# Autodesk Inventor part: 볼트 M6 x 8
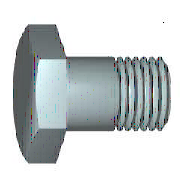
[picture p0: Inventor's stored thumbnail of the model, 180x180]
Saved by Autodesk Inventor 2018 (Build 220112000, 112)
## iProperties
Created: 2012-02
Part Number: 볼트 M6 x 8
Material: 강철, 연강
Description: 6각 머리 볼트 및 6각 머리 나사
Document SubType Name: Modeling
Standard: KS B 1002
Designer: mduedu
Standards Organization: KS
Language: ko-KR
Size Designation: C  M 6 x 12
Categories: <MemberInstance><Categories><Category DisplayName="조임쇠" InternalName="e4da775c-781d-43d5-af7c-5136215cf5a6" Mnemonic="FSTN"><Category DisplayName="볼트" InternalN
Density: 7.86 g/cm^3
Mass: 4.46616 g
Surface Area: 4.51243 cm^2
Volume: 0.568214 cm^3
Appearance: 강철
IsCustomPart: 1
Author: mduedu
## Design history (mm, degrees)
sketch "스케치1"
  geometry: L1 (0, 3)-(8, 3); L2 (8, 3)-(8, 0); L3 (8, 0)-(0, 0); L4 (-2.4, 0)-(14.4, 0) reference; L5 (0, -0.6)-(0, 3.6) reference; L6 (0, 3)-(0, 0)
  constraints: 8 end point, 3 point on line, 1 collinear
  dimensions: "d2" = 6 diameter of L1 L3 (= GD); "d59" = 8 distance between parallel lines of L2 L5 (= NLG)
revolve "본체" sketch "스케치1" stored, may be unused: angle "d12" = 90 deg
sketch "스케치2"
  geometry: L1 (0, 5.774)-(5, 2.887); L2 (5, 2.887)-(5, -2.887); L3 (5, -2.887)-(0, -5.774); L4 (0, -5.774)-(-5, -2.887); L5 (-5, -2.887)-(-5, 2.887); L6 (-5, 2.887)-(0, 5.774); L7 (-7, 0)-(7, 0) reference; L8 (0, 8.083)-(0, -8.083) reference; 2 further points
  constraints: 12 end point, 2 midpoint, 1 coincident, 1 vertical, 11 other
  dimensions: "d11" = 10 distance between parallel lines of L5 L2 (= SW)
extrude "머리" join sketch "스케치2" distance "d3" = 4 (= KOH); taper "d4" = 0 deg
revolve "모따기1" stored, may be unused: angle "d21" = 90 deg
workplane "Work Plane1"
body "Solid1"
feature "스레드" dims "d15" = 9 (= GEL), "d16" = 0
chamfer "모따기2" distance "d6" = 0.61345 (= -0.5 x SPD + 0.5 x GD); stored, may be unused: second distance "d7" = 0.61355 (computed from GUL), angle "d55" = 45 deg
sketch "스케치4"
  geometry: L1 (-3.423, 6)-(-4, 5); L2 (-1.1, 0)-(-0.234, 0); L3 (-4.753, 0)-(0.519, 0) reference; L4 (-4, 6)-(-3.423, 6); L5 (-4, 5)-(-4, 6); L6 (0, 7.2)-(0, -1.2) reference
  constraints: 8 end point, 1 parallel, 1 perpendicular, 1 point on line
  dimensions: "d65" = 10 diameter of L1.end L2 (= SW); "d67" = 30 deg angle of L1 L5 (= ANG1); "d68" = 12 diameter of L4 L2 (= 1.2 x SW); "d69" = 4 distance between parallel lines of L5 L6 (= KOH)
other parameters: "NLG" = 8 [user parameter; used in 1 equation term], "GD" = 6 (= NND) [user parameter; used in 2 equation terms], "BDM" = 6 (= NND) [user parameter], "KOH" = 4 [user parameter; used in 2 equation terms], "GEL" = 9 [user parameter; used in 1 equation term], "SW" = 10 [user parameter; used in 5 equation terms], "SPD" = 4.7731 (= NND - 1.2269 x PTC) [user parameter; used in 1 equation term], "SD2" = 6 (= NND) [user parameter], "SD" = 0 [user parameter], "ANG1" = 30 deg [user parameter; used in 1 equation term], "GAL" = 0.61345 (= 0.61345 x PTC) [user parameter], "GUL" = 0.61345 (= 0.61345 x PTC) [user parameter; used in 1 equation term], "d8" = 0, "RR" = 0.25 [user parameter], "d58" = 0, "RR1" = 0.1 [user parameter], "GD1" = 4.7731 (= THREADDIA - 1.2269 x PTC) [user parameter], "THREADDIA" = 6 [user parameter; used in 1 equation term], "TOA" = 30 deg [user parameter], "PTC" = 1 [user parameter; used in 5 equation terms], "NND" = 6 [user parameter; used in 4 equation terms], "E0" = 11.55 (= 1.155 x SW) [user parameter]
